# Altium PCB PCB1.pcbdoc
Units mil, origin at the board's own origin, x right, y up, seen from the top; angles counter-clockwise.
Board outline 12930 x 2655 mil, 2 copper layers (Top Layer, Bottom Layer); 71 components, 40 nets, 158 pads, 0 vias.
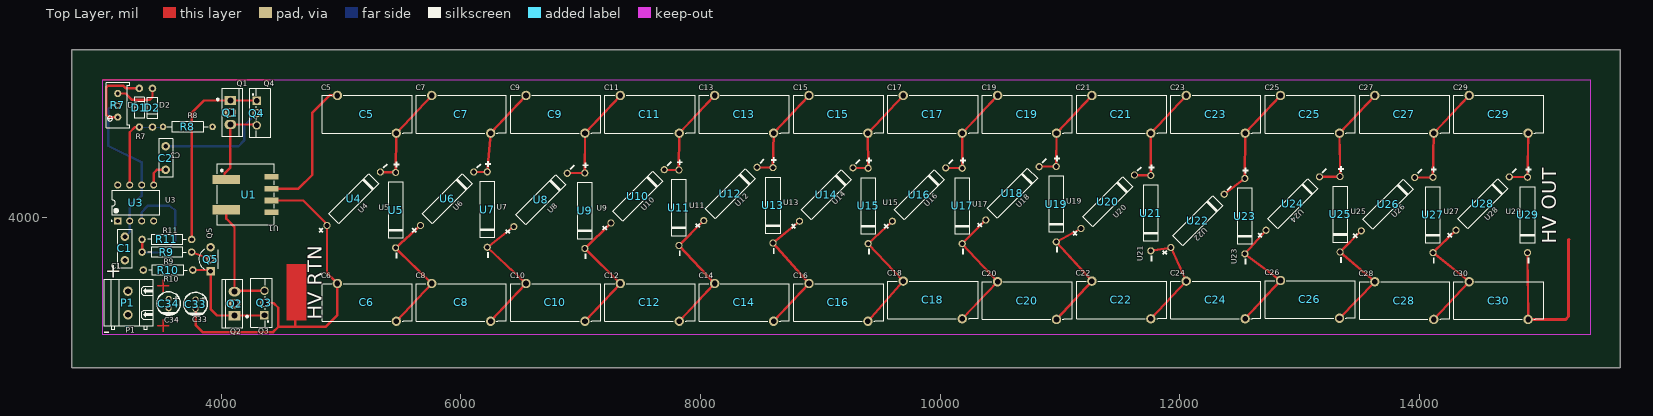
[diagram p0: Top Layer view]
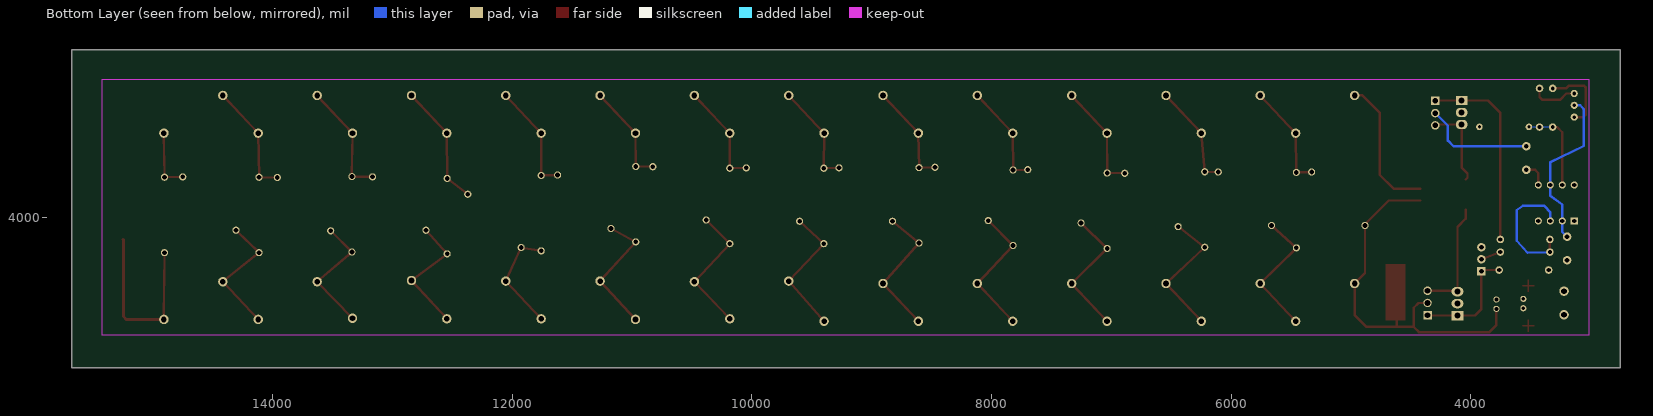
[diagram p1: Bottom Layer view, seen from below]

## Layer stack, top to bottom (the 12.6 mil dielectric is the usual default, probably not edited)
Top Layer: signal copper (thickness not stored)
Dielectric: dielectric 12.6, FR-4, Dk 4.8
Bottom Layer: signal copper (thickness not stored)

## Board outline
15680,2750 2750,2750 2750,5405 15680,5405

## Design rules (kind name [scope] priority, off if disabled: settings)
BoardOutlineClearance copperThickness1oz [All] p0: genericclearance=10 ignorepadtopadclearanceinfootprint=FALSE except(0: Arc-SplitContinuation Track-SplitContinuation SMDPad-SplitContinuation THPad-SplitContinuation Via-SplitContinuation Fill-SplitContinuation Poly-SplitContinuation Region-SplitContinuation Text-SplitContinuation; 6: Track-CutoutEdge SMDPad-CutoutEdge THPad-CutoutEdge Via-CutoutEdge Region-CutoutEdge; 11.8: Track-OutlineEdge SMDPad-OutlineEdge THPad-OutlineEdge Via-OutlineEdge Fill-OutlineEdge Region-OutlineEdge Poly-OutlineEdge Text-OutlineEdge Fill-CutoutEdge)
BoardOutlineClearance copperThickness2oz [All] p0: genericclearance=10 ignorepadtopadclearanceinfootprint=FALSE except(0: Arc-SplitContinuation Track-SplitContinuation SMDPad-SplitContinuation THPad-SplitContinuation Via-SplitContinuation Fill-SplitContinuation Poly-SplitContinuation Region-SplitContinuation Text-SplitContinuation; 6: Track-CutoutEdge SMDPad-CutoutEdge THPad-CutoutEdge Via-CutoutEdge Region-CutoutEdge; 11.8: Track-OutlineEdge SMDPad-OutlineEdge THPad-OutlineEdge Via-OutlineEdge Fill-OutlineEdge Region-OutlineEdge Poly-OutlineEdge Text-OutlineEdge Fill-CutoutEdge)
Clearance copperThickness1oz [(InNet('TRIG') OR InNet('GND') OR InNet('$1N1749') OR InNet('$1N2141') OR InNet('$1N4334') OR InNet('$1N2190') OR InNet('$1N2475') OR InNet('$1N2479') OR InNet('$1N2619') OR InNet('$1N2623') OR InNet('$1N2763') OR InNet('$1N2767') OR InNet('$1N2907') OR InNet('$1N2911') OR InNet('$1N3051') OR InNet('$1N3055') OR InNet('$1N3195') OR InNet('$1N3199') OR InNet('$1N3339') OR InNet('$1N3343') OR InNet('$1N4268') OR InNet('$1N4243') OR InNet('$1N4271') OR InNet('$1N3631') OR InNet('$1N4211') OR InNet('$1N3775') OR InNet('$1N4214') OR InNet('$1N3919') OR InNet('NET5') OR InNet('$1N4063') OR InNet('VCC') OR InNet('$1N1755') OR InNet('$1N1693') OR InNet('$1N1691') OR InNet('$1N1044') OR InNet('$1N998') OR InNet('$1N1038') OR InNet('$1N872') OR InNet('$1N1125') OR InNet('$1N1129'))] p1: gap=7 ignorepadtopadclearanceinfootprint=FALSE except(4: Track-Track; 6: Track-SMDPad SMDPad-SMDPad Track-THPad SMDPad-THPad THPad-THPad Track-Via SMDPad-Via THPad-Via Via-Via SMDPad-Fill THPad-Fill Via-Fill Fill-Fill Track-Region SMDPad-Region THPad-Region Via-Region Region-Region Track-Poly SMDPad-Poly THPad-Poly Via-Poly Fill-Poly Region-Poly Poly-Poly Track-Text SMDPad-Text THPad-Text Via-Text Fill-Text Region-Text Poly-Text Text-Text; 6.9: Track-Hole SMDPad-Hole THPad-Hole Via-Hole Fill-Hole Region-Hole Poly-Hole Text-Hole Sheet-Hole; 11.8: Track-Fill Fill-Region Track-Sheet SMDPad-Sheet THPad-Sheet Via-Sheet Fill-Sheet Region-Sheet Poly-Sheet Text-Sheet)
Clearance copperThickness2oz [All] p1: gap=7 ignorepadtopadclearanceinfootprint=FALSE except(6: Track-SMDPad SMDPad-SMDPad Track-THPad SMDPad-THPad THPad-THPad Track-Via SMDPad-Via THPad-Via Via-Via SMDPad-Fill THPad-Fill Via-Fill Fill-Fill Track-Region SMDPad-Region THPad-Region Via-Region Region-Region Track-Poly SMDPad-Poly THPad-Poly Via-Poly Fill-Poly Region-Poly Poly-Poly Track-Text SMDPad-Text THPad-Text Via-Text Fill-Text Region-Text Poly-Text Text-Text; 6.9: Track-Hole SMDPad-Hole THPad-Hole Via-Hole Fill-Hole Region-Hole Poly-Hole Text-Hole Sheet-Hole; 8: Track-Track; 11.8: Track-Fill Fill-Region Track-Sheet SMDPad-Sheet THPad-Sheet Via-Sheet Fill-Sheet Region-Sheet Poly-Sheet Text-Sheet)
DiffPairsRouting differentialPair [All] p1: maxuncoupledlength=10 minlimit=6 maxlimit=6 mostfreqgap=6 toplayer_minwidth=5 toplayer_prefwidth=10 toplayer_maxwidth=100 bottomlayer_minwidth=5 bottomlayer_prefwidth=10 bottomlayer_maxwidth=100
PasteMaskExpansion pasteMaskExpansion [All] p1: expansion=0
PlaneConnect innerPlane [All] p1: planeconnectstyle=Relief reliefexpansion=20 reliefentries=4 reliefconductorwidth=10 reliefairgap=10
PolygonConnect copperRegion [All] p1: connectstyle=Relief reliefentries=4 reliefconductorwidth=10 polygonreliefangle="90 Angle" airgapwidth=10
RoutingVias viaSize [All] p1: viastyle="Through Hole" holewidth=12.0078 minholewidth=11.811 maxholewidth=248.0314 width=24.0158 minwidth=19.685 maxwidth=393.7008
SolderMaskExpansion solderMaskExpansion [All] p1: useseparateexpansions=TRUE expansion=2 expansionbottom=2
Width copperThickness1oz [All] p1: maxlimit=100 minlimit=5 preferedwidth=10
Width copperThickness2oz [All] p1: maxlimit=100 minlimit=8 preferedwidth=10

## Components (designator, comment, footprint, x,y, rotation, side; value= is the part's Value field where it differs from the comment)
C1 "R08B1B102KN0B0S0N0" CAP-TH_L8.0-W3.0-P5.0-D0.60 3195,3745 r90 top
C2 "R08B1B102KN0B0S0N0" CAP-TH_L8.0-W3.0-P5.0-D0.60 3535,4500 r270 top
C5 "HVCC153Y6P202MEAX" CAP-TH_L19.0-W8.0-P12.50-D0.8-S8.0 5214.76,4865 r0 top
C6 "HVCC153Y6P202MEAX" CAP-TH_L19.0-W8.0-P12.50-D0.8-S8.0 5214.76,3294.96 r0 top
C7 "HVCC153Y6P202MEAX" CAP-TH_L19.0-W8.0-P12.50-D0.8-S8.0 6002.17,4865 r0 top
C8 "HVCC153Y6P202MEAX" CAP-TH_L19.0-W8.0-P12.50-D0.8-S8.0 6002.17,3294.96 r0 top
C9 "HVCC153Y6P202MEAX" CAP-TH_L19.0-W8.0-P12.50-D0.8-S8.0 6789.57,4865 r0 top
C10 "HVCC153Y6P202MEAX" CAP-TH_L19.0-W8.0-P12.50-D0.8-S8.0 6789.57,3294.96 r0 top
C11 "HVCC153Y6P202MEAX" CAP-TH_L19.0-W8.0-P12.50-D0.8-S8.0 7576.97,4865 r0 top
C12 "HVCC153Y6P202MEAX" CAP-TH_L19.0-W8.0-P12.50-D0.8-S8.0 7576.97,3294.96 r0 top
C13 "HVCC153Y6P202MEAX" CAP-TH_L19.0-W8.0-P12.50-D0.8-S8.0 8364.37,4865 r0 top
C14 "HVCC153Y6P202MEAX" CAP-TH_L19.0-W8.0-P12.50-D0.8-S8.0 8364.37,3294.96 r0 top
C15 "HVCC153Y6P202MEAX" CAP-TH_L19.0-W8.0-P12.50-D0.8-S8.0 9151.77,4865 r0 top
C16 "HVCC153Y6P202MEAX" CAP-TH_L19.0-W8.0-P12.50-D0.8-S8.0 9151.77,3294.96 r0 top
C17 "HVCC153Y6P202MEAX" CAP-TH_L19.0-W8.0-P12.50-D0.8-S8.0 9939.17,4865 r0 top
C18 "HVCC153Y6P202MEAX" CAP-TH_L19.0-W8.0-P12.50-D0.8-S8.0 9939.17,3315 r0 top
C19 "HVCC153Y6P202MEAX" CAP-TH_L19.0-W8.0-P12.50-D0.8-S8.0 10726.57,4865 r0 top
C20 "HVCC153Y6P202MEAX" CAP-TH_L19.0-W8.0-P12.50-D0.8-S8.0 10726.57,3310 r0 top
C21 "HVCC153Y6P202MEAX" CAP-TH_L19.0-W8.0-P12.50-D0.8-S8.0 11513.98,4865 r0 top
C22 "HVCC153Y6P202MEAX" CAP-TH_L19.0-W8.0-P12.50-D0.8-S8.0 11513.98,3315 r0 top
C23 "HVCC153Y6P202MEAX" CAP-TH_L19.0-W8.0-P12.50-D0.8-S8.0 12301.38,4865 r0 top
C24 "HVCC153Y6P202MEAX" CAP-TH_L19.0-W8.0-P12.50-D0.8-S8.0 12301.38,3315 r0 top
C25 "HVCC153Y6P202MEAX" CAP-TH_L19.0-W8.0-P12.50-D0.8-S8.0 13088.78,4865 r0 top
C26 "HVCC153Y6P202MEAX" CAP-TH_L19.0-W8.0-P12.50-D0.8-S8.0 13088.78,3320 r0 top
C27 "HVCC153Y6P202MEAX" CAP-TH_L19.0-W8.0-P12.50-D0.8-S8.0 13876.18,4865 r0 top
C28 "HVCC153Y6P202MEAX" CAP-TH_L19.0-W8.0-P12.50-D0.8-S8.0 13876.18,3310 r0 top
C29 "HVCC153Y6P202MEAX" CAP-TH_L19.0-W8.0-P12.50-D0.8-S8.0 14663.58,4865 r0 top
C30 "HVCC153Y6P202MEAX" CAP-TH_L19.0-W8.0-P12.50-D0.8-S8.0 14663.58,3310 r0 top
C33 "GR226M050D11RR0VH4FP0" CAP-TH_BD5.0-P2.00-D0.8-FD 3785,3280 r270 top
C34 "GR226M050D11RR0VH4FP0" CAP-TH_BD5.0-P2.00-D0.8-FD 3560,3285 r270 top
D1 "1N4148_C402212" DO-35_BD2.0-L4.2-P8.20-D0.5-RD 3315,4920 r270 top
D2 "1N4148_C402212" DO-35_BD2.0-L4.2-P8.20-D0.5-RD 3425,4920 r90 top
P1 "WJ128V-5.0-2P" CONN-TH_2P-P5.00_WJ128V-5.0-2P 3220,3290 r90 top
Q1 "TIP41C_C92310" TO-220-3_L10.0-W4.5-P2.54-T 4075,4880 r0 top
Q2 "TIP41C_C92310" TO-220-3_L10.0-W4.5-P2.54-T 4110,3285 r180 top
Q3 "TIP42C_C410524" ITO-220AB-3_L10.2-W4.5-P2.60-L 4360,3290 r90 top
Q4 "TIP42C_C410524" ITO-220AB-3_L10.2-W4.5-P2.60-L 4295,4875 r270 top
Q5 "BC547CTA" TO-92-3_L4.8-W3.7-P2.54-L 3910,3655 r90 top
R7 "3296W-1-103_C118954" RES-ADJ-TH_3P-L10.0-W10.0-P2.50-L 3135,4940 r90 top
R8 "MF1/4W-1KΩ±1%T52" RES-TH_BD2.3-L6.5-P10.50-D0.5 3720,4760 r0 top
R9 "CFR0W4J0512A50" RES-TH_BD2.2-L6.5-P10.50-D0.6 3545,3715 r0 top
R10 "CFR0W4J0512A50" RES-TH_BD2.2-L6.5-P10.50-D0.6 3555,3565 r180 top
R11 "MFR0W4F2001A50" RES-TH_BD2.2-L6.5-P10.50-D0.6 3545,3820 r0 top
U1 "FC-SCT1010-1:200T-40A" XFMR-SMD_6P-P2.50_FC-SCT1010 4230,4195 r180 top
U3 "NE555P" DIP-8_L9.8-W6.6-P2.54-LS7.6-BL 3285,4125 r0 top
U4 "2CL77" DIO-TH_BD3.0-L12.0-P16.00-D0.6 5105,4160 r225 top
U5 "2CL77" DIO-TH_BD3.0-L12.0-P16.00-D0.6 5455,4065 r90 top
U6 "2CL77" DIO-TH_BD3.0-L12.0-P16.00-D0.6 5885,4160 r225 top
U7 "2CL77" DIO-TH_BD3.0-L12.0-P16.00-D0.6 6220,4070 r90 top
U8 "2CL77" DIO-TH_BD3.0-L12.0-P16.00-D0.6 6665,4150 r225 top
U9 "2CL77" DIO-TH_BD3.0-L12.0-P16.00-D0.6 7035,4060 r90 top
U10 "2CL77" DIO-TH_BD3.0-L12.0-P16.00-D0.6 7475,4180 r225 top
U11 "2CL77" DIO-TH_BD3.0-L12.0-P16.00-D0.6 7820,4085 r90 top
U12 "2CL77" DIO-TH_BD3.0-L12.0-P16.00-D0.6 8250,4200 r225 top
U13 "2CL77" DIO-TH_BD3.0-L12.0-P16.00-D0.6 8605,4105 r90 top
U14 "2CL77" DIO-TH_BD3.0-L12.0-P16.00-D0.6 9050,4195 r225 top
U15 "2CL77" DIO-TH_BD3.0-L12.0-P16.00-D0.6 9400,4100 r90 top
U16 "2CL77" DIO-TH_BD3.0-L12.0-P16.00-D0.6 9825,4195 r225 top
U17 "2CL77" DIO-TH_BD3.0-L12.0-P16.00-D0.6 10185,4100 r90 top
U18 "2CL77" DIO-TH_BD3.0-L12.0-P16.00-D0.6 10605,4205 r225 top
U19 "2CL77" DIO-TH_BD3.0-L12.0-P16.00-D0.6 10970,4115 r90 top
U20 "2CL77" DIO-TH_BD3.0-L12.0-P16.00-D0.6 11400,4135 r225 top
U21 "2CL77" DIO-TH_BD3.0-L12.0-P16.00-D0.6 11760,4040 r90 top
U22 "2CL77" DIO-TH_BD3.0-L12.0-P16.00-D0.6 12150,3975 r225 top
U23 "2CL77" DIO-TH_BD3.0-L12.0-P16.00-D0.6 12545,4015 r90 top
U24 "2CL77" DIO-TH_BD3.0-L12.0-P16.00-D0.6 12945,4120 r225 top
U25 "2CL77" DIO-TH_BD3.0-L12.0-P16.00-D0.6 13340,4030 r90 top
U26 "2CL77" DIO-TH_BD3.0-L12.0-P16.00-D0.6 13740,4115 r225 top
U27 "2CL77" DIO-TH_BD3.0-L12.0-P16.00-D0.6 14115,4025 r90 top
U28 "2CL77" DIO-TH_BD3.0-L12.0-P16.00-D0.6 14530,4120 r225 top
U29 "2CL77" DIO-TH_BD3.0-L12.0-P16.00-D0.6 14905,4025 r90 top

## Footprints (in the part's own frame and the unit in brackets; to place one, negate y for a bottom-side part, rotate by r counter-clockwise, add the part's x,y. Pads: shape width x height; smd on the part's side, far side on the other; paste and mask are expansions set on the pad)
CAP-TH_BD5.0-P2.00-D0.8-FD [mm]
  round 1.3 hole 0.8: 1(-1,0) 2(1,0)
  silkscreen extent -2.5,-2.5 2.5,2.5
CAP-TH_L8.0-W3.0-P5.0-D0.60 [mm]
  round 1.8 hole 1: 1(-2.5,0) 2(2.5,0)
  silkscreen extent -4.1,-1.5 4.1,1.5
CAP-TH_L19.0-W8.0-P12.50-D0.8-S8.0 [mm]
  round 2 hole 1.2: 1(-6.25,4) 2(6.25,-4)
  silkscreen extent -9.5,-4 9.5,4
CONN-TH_2P-P5.00_WJ128V-5.0-2P [mm]
  round 2 hole 1.2: 1(-2.504,0) 2(2.504,0)
  silkscreen extent -5.55,-5.4 5.05,5
DIO-TH_BD3.0-L12.0-P16.00-D0.6 [mil]
  round 60 hole 39.37: 1(-314.96,0) 2(314.96,0)
  silkscreen extent -403,-59 403,59
DIP-8_L9.8-W6.6-P2.54-LS7.6-BL [mm]
  rect 1.5x1.5 hole 0.9: 1(-3.81,-3.81)
  round 1.5 hole 0.9: 2(-1.27,-3.81) 3(1.27,-3.81) 4(3.81,-3.81) 5(3.81,3.81) 6(1.27,3.81) 7(-1.27,3.81) 8(-3.81,3.81)
  silkscreen extent -5.23,-3.93 4.96,2.65
DO-35_BD2.0-L4.2-P8.20-D0.5-RD [mm]
  round 1.6 hole 0.8: 1(-4.1,0) 2(4.1,0)
  silkscreen extent -2.2,-1.1 2.2,1.1
ITO-220AB-3_L10.2-W4.5-P2.60-L [mm]
  rect 1.8x1.8 hole 1.2: 1(-2.6,0)
  round 1.8 hole 1.2: 2(0,0) 3(2.6,0)
  silkscreen extent -5.2,-1.6 5.2,2.9
RES-ADJ-TH_3P-L10.0-W10.0-P2.50-L [mil]
  round 60 hole 30: 1(-98.43,0) 2(0,0) 3(98.43,0)
  silkscreen extent -187,-98 187,96
RES-TH_BD2.2-L6.5-P10.50-D0.6 [mm]
  round 1.6 hole 0.914: 1(-5.25,0) 2(5.25,0)
  silkscreen extent -4.06,-1.14 4.06,1.14
RES-TH_BD2.3-L6.5-P10.50-D0.5 [mm]
  round 1.4 hole 0.7: 1(-5.25,0) 2(5.25,0)
  silkscreen extent -4.32,-1.15 4.32,1.15
TO-92-3_L4.8-W3.7-P2.54-L [mm]
  rect 1.8x1.8 hole 1: 1(-2.54,0)
  round 1.8 hole 1: 2(0,0) 3(2.54,0)
  silkscreen extent -2.17,-1.5 2.14,2.48
TO-220-3_L10.0-W4.5-P2.54-T [mm]
  rect 2.5x2 hole 1.3: 1(0,2.54)
  oval 2.5x2 hole 1.3: 2(0,0) 3(0,-2.54)
  silkscreen extent -2.86,-5.08 2.67,5.08
XFMR-SMD_6P-P2.50_FC-SCT1010 [mm]
  rect 5.8x2 smd: 1(4.8,-3.2) 2(4.8,3.2)
  rect 3x1.2 smd: 3(-4.8,3.75) 4(-4.8,1.25) 5(-4.8,-1.25) 6(-4.8,-3.75)
  silkscreen extent -5.4,-6.4 6.8,6.4

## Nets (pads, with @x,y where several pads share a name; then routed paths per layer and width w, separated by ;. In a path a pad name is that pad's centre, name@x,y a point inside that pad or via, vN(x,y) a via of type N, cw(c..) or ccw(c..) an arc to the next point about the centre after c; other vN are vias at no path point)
$1N872: Q2.3 Q3.3 U1.2 | length 965.6
  Top Layer w20: U1.2 4041.03,3994.02 4110,3925.05 Q2.3 4117.36,3392.36 Q3.3
$1N998: Q1.3 Q4.3 U1.1 | length 708.6
  Top Layer w20: U1.1 4026.03,4335.99 4026.03,4371.02 4075,4420 Q1.3 4287.64,4780 Q4.3
$1N1038: Q2.1 Q3.1 Q5.1 R10.1 | length 941.3
  Top Layer w20: R10.1 3900,3565 Q5.1 3910,3240 3965,3185 Q2.1 4357.36,3185 Q3.1
$1N1044: Q1.1 Q4.1 R11.2 | length 1643.9
  Top Layer w20: R11.2 3751.7,4876.69 3855,4980 Q1.1 4292.36,4980 Q4.1
$1N1125: Q5.2 R9.2 | length 169.3
  Top Layer w20: R9.2 Q5.2
$1N1129: R9.1 R11.1 U3.3 | length 1066.7
  Top Layer w20: R9.1 R11.1
  Bottom Layer w20: U3.3 3335,4045 3385,4100 3565,4100 3615,4065 3615,3810 3525,3710 R9.1
$1N1691: D2.2 R7.3 | length 393.9
  Top Layer w20: R7.3 3201.57,5038.43 3255,4985 3400,4985 3425,5010 D2.2
$1N1693: D1.1 R7.1 | length 624.9
  Top Layer w20: R7.1 3133.43,4840 3060,4840 3040,4860 3040,5090 3055,5105 3180,5105 3203.58,5081.42 D1.1
$1N1749: C2.2 U3.5 | length 211
  Top Layer w20: U3.5 3435,4375 3461.58,4401.58 C2.2
$1N1755: D1.2 D2.1 R8.1 U3.7 | length 736.9
  Top Layer w20: U3.7 3235,4715 3278.58,4758.58 D1.2
  Bottom Layer w10: D1.2 D2.1 3511.89,4758.58 R8.1
$1N2141: C5.2 C7.1 U4.1 U5.2 | length 886.7
  Top Layer w20: U4.1 U5.2 C5.2 C7.1
$1N2190: C6.2 C8.1 U5.1 U6.2 | length 1134.4
  Top Layer w20: C6.2 C8.1 U5.1 U6.2
$1N2475: C7.2 C9.1 U6.1 U7.2 | length 867.8
  Top Layer w20: U6.1 U7.2 C7.2 C9.1
$1N2479: C8.2 C10.1 U7.1 U8.2 | length 1155.9
  Top Layer w20: C8.2 C10.1 U7.1 U8.2
$1N2619: C9.2 C11.1 U8.1 U9.2 | length 911.6
  Top Layer w20: U8.1 U9.2 C9.2 C11.1
$1N2623: C10.2 C12.1 U9.1 U10.2 | length 1151.6
  Top Layer w20: C10.2 C12.1 U9.1 U10.2
$1N2763: C11.2 C13.1 U10.1 U11.2 | length 861.6
  Top Layer w20: U10.1 U11.2 C11.2 C13.1
$1N2767: C12.2 C14.1 U11.1 U12.2 | length 1160.6
  Top Layer w20: C12.2 C14.1 U11.1 U12.2
$1N2907: C13.2 C15.1 U12.1 U13.2 | length 851.7
  Top Layer w20: U12.1 U13.2 C13.2 C15.1
$1N2911: C14.2 C16.1 U13.1 U14.2 | length 1171.3
  Top Layer w20: C14.2 C16.1 U13.1 U14.2
$1N3051: C15.2 C17.1 U14.1 U15.2 | length 851.6
  Top Layer w20: U14.1 U15.2 C15.2 C17.1
$1N3055: C16.2 C18.1 U15.1 U16.2 | length 1150.7
  Top Layer w20: C16.2 C18.1 U15.1 U16.2
$1N3195: C17.2 C19.1 U16.1 U17.2 | length 861.6
  Top Layer w20: U16.1 U17.2 C17.2 C19.1
$1N3199: C18.2 C20.1 U17.1 U18.2 | length 1140.9
  Top Layer w20: C18.2 C20.1 U17.1 U18.2
$1N3339: C19.2 C21.1 U18.1 U19.2 | length 851.6
  Top Layer w20: U18.1 U19.2 C19.2 C21.1
$1N3343: C20.2 C22.1 U19.1 U20.2 | length 1113.9
  Top Layer w20: C20.2 C22.1 U19.1 U20.2
$1N3631: C24.2 C26.1 U23.1 U24.2 | length 1072.3
  Top Layer w20: C24.2 C26.1 U23.1 U24.2
$1N3775: C26.2 C28.1 U25.1 U26.2 | length 1056.6
  Top Layer w20: C26.2 C28.1 U25.1 U26.2
$1N3919: C28.2 C30.1 U27.1 U28.2 | length 1087.9
  Top Layer w20: C28.2 C30.1 U27.1 U28.2
$1N4063: C30.2 U29.1 | length 1549.9
  Top Layer w20: U29.1 C30.2
  Top Layer w24: C30.2 15223.52,3152.52 15247.52,3176.52 15247.52,3817.52 15250,3820
$1N4211: C25.2 C27.1 U24.1 U25.2 | length 966.6
  Top Layer w20: U24.1 U25.2 C25.2 C27.1
$1N4214: C27.2 C29.1 U26.1 U27.2 | length 951.7
  Top Layer w20: U26.1 U27.2 C27.2 C29.1
$1N4243: C22.2 C24.1 U21.1 U22.2 | length 908.9
  Top Layer w20: U21.1 U22.2 C24.1 C22.2
$1N4268: C21.2 C23.1 U20.1 U21.2 | length 921.6
  Top Layer w20: U20.1 U21.2 C21.2 C23.1
$1N4271: C23.2 C25.1 U22.1 U23.2 | length 1026.5
  Top Layer w20: U22.1 U23.2 C23.2 C25.1
$1N4334: C5.1 U1.5 | length 1176.7
  Top Layer w20: U1.5 4644.21,4244.21 4760,4360 4760,4880 4902.48,5022.48 C5.1
GND: C1.1 C2.1 C6.1 C33.2 C34.2 P1.1 Q3.2 Q4.2 Q5.3 U1.4 U3.1 U4.2 | length 4107.8
  Top Layer w20: C33.2 3785,3105 3843.19,3046.81 4431.81,3046.81 4475,3090 ; Q3.2 4435,3290 4475,3250 4475,3090 ; U1.4 4683.79,4145.79 4882.29,3947.29 U4.2 4882.29,3538.85 C6.1 4968.7,3188.7 4870,3090 4616.92,3090 ; 4620,3215 4616.92,3211.92 4616.92,3090 ; 4475,3090 4616.92,3090
  Bottom Layer w20: C2.1 4143.43,4598.43 4190,4645 4190,4770 Q4.2
NET5: C29.2 U28.1 U29.2 | length 519.9
  Top Layer w20: U28.1 U29.2 C29.2
TRIG: C1.2 R7.2 U3.2 U3.6 | length 1400.1
  Bottom Layer w20: R7.2 3085,4940 3055,4905 3055,4600 3335,4465 U3.6 3335,4185 3235,4110 U3.2 3235,3883.42 C1.2
VCC: C33.1 C34.1 P1.2 Q1.2 Q2.2 R8.2 R10.2 U3.4 U3.8
pads on no net: U1.3 U1.6

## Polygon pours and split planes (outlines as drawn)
GND on Top Layer (solid, remove dead copper, pour order 0): 3010,5155 4401.28,5155 4401.28,5154.9 3010,5154.9
GND on Top Layer (solid, remove dead copper, pour order 2): 3010,5155 4216.55,5155 4216.55,3025 3010,3025
VCC on Bottom Layer (solid, remove dead copper, pour order 6): 3000,5155 4206.32,5155 4206.32,3025 3000,3025
$1N4063 on Top Layer (solid, remove dead copper, pour order 4): 15165,4315 15370,4315 15370,3725 15165,3725

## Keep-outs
Board Outline Layer:
  lines w10: 3010,3025 15430,3025 15430,5155 3010,5155 3010,3025

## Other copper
Top Layer:
  region net GND: 4545,3615 4710,3615 4710,3145 4545,3145
  region net GND: 4545,3615 4710,3615 4710,3145 4545,3145
  text "+" at 3450,3380 h120
  text "+" at 3450,3045 h120

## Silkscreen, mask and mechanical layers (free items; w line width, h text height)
Top Silkscreen Layer:
  text "HV OUT" at 15145,3785 h120 r90
  text "+" at 3030,3500 h120
  text "HV RTN" at 4840,3150 h120 r90
  text "-" at 3015,3000 h120
Top Solder Mask Layer:
  region: 4545,3615 4710,3615 4710,3145 4545,3145
  region: 15165,4315 15370,4315 15370,3725 15165,3725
